AutomationDirect Productivity Suite project: Saginaw_ModbusRTU_v2 (software 3.11.0 (26))
author: charris
Rung notation: left to right = series (deeper-indented lines continue the line above), [a | b] = parallel branches, -- = plain wire, BOX.Pin = further input of the box above; 'quoted' = tag name, ? = field left empty; instruction and field names as stored in the project; options that are off are not listed.

HARDWARE
  Base 1 (5 slots)
    slot 0: P2-550

STRUCTURES
STRUCTURE read_Data
  net_Cool_SP : Int16, strLength=15
  net_HighTempAlmSP : Int16, strLength=15
  net_LowTempAlmSP : Int16, strLength=15
  net_Heat_SP : Int16, strLength=15
  net_Enable_Flags : Uint16, strLength=15
  Control_SP : Int16, strLength=15
  High_Temp_SP : Int16, strLength=15
  Low_Temp_SP : Int16, strLength=15
  Heater_SP : Int16, strLength=15
  Temp_POT : Int16, strLength=15
  Alarm_POT : Int16, strLength=15
  Heater_POT : Int16, strLength=15
  Control_Sensor : Int16, strLength=15
  State : Uint16, strLength=15
  Alarm_Stat : Uint16, strLength=15
  Output_Stat : Uint16, strLength=15
  Contact_Stat : Uint16, strLength=15
  IntAir_Outlet_Temp : Int16, strLength=15
  Ambient_Temp : Int16, strLength=15
  Act_Spd_int_Blow : Uint16, strLength=15
  Act_Spd_Amb_Blow : Uint16, strLength=15
  Act_Spd_Compress : Uint16, strLength=15
  Set_Spd_int_Blow : Uint16, strLength=15
  Set_Spd_Amb_Blow : Uint16, strLength=15
  Set_Spd_Compress : Uint16, strLength=15
  Alm_int_Blow : Uint16, strLength=15
  Alm_Amb_Blow : Uint16, strLength=15
  Alm_Compress : Uint16, strLength=15
STRUCTURE write_Data
  net_Cool_SP : Int16, strLength=15
  net_HighTempAlmSP : Int16, strLength=15
  net_LowTempAlmSP : Int16, strLength=15
  net_Heat_SP : Int16, strLength=15
  net_Enable_Flags : Uint16, strLength=15

TAGS  (name : type @system ID = initial value)
  readBuff1 : Array[50] of Uint16 @AR1US16-000001
  readBuff2 : Array[50] of Uint16 @AR1US16-000002
  readUnit1 : read_Data @USTRUC-000001
  readUnit2 : read_Data @USTRUC-000002
  writeUnit1 : write_Data @USTRUC-000003
  writeUnit2 : write_Data @USTRUC-000004
  writeBuff1 : Array[10] of Uint16 @AR1US16-000003
  writeBuff2 : Array[10] of Uint16 @AR1US16-000004
  Synch_Unit1_SP_Data : Boolean @C-000017
  Update_Unit1_SP : Boolean @C-000018
  Unit1_New_CoolSP : Int16 @S16-000037
  Update_Unit1_Flags : Boolean @C-000024
  Synch_Unit2_SP_Data : Boolean @C-000030
  Update_Unit2_SP : Boolean @C-000031
  Unit2_New_CoolSP : Int16 @S16-000038
  Update_Unit2_Flags : Boolean @C-000037
  Change_Node_Address : Boolean @C-000043
  Node_Number : Uint16 @US16-000031
  Write_Node_Number : Boolean @C-000044
  NodeNum_PrepWrite_Succ : Boolean @C-000050
  Disable_Reads : Boolean @C-000051
  Unit1_OutStat_AmbBlower : Boolean @C-000052
  Unit1_OutStat_Compressor : Boolean @C-000053
  Unit1_OutStat_Heater : Boolean @C-000054
  Unit1_OutStat_IntBlower : Boolean @C-000055
  EnableFlags : Int16 @S16-000039

SYSTEM TAGS USED OR MAPPED TO MODBUS
  'First Scan Bit' : Boolean @SBR-001003  // On during first scan in Run or Debug mode
  rComSuccessCNT : SCNT @SSTRUC-000001  // System Structure for Simple Counter
  rComErrorCNT : SCNT @SSTRUC-000002  // System Structure for Simple Counter
  ComSequenceTMR : STMR @SSTRUC-000003  // System Structure for Simple Timer
  ComSequenceCNT : SCNT @SSTRUC-000004  // System Structure for Simple Counter
  MRXUnit1 : MRX @SSTRUC-000005  // System Structure for Modbus Read
  MRXUnit2 : MRX @SSTRUC-000006  // System Structure for Modbus Read
  MWX_Chg_Node : MWX @SSTRUC-000013  // System Structure for Modbus Write
  MWXUnit1 : MWX @SSTRUC-000014  // System Structure for Modbus Write
  MWXUnit1b : MWX @SSTRUC-000015  // System Structure for Modbus Write
  MWXUnit2 : MWX @SSTRUC-000016  // System Structure for Modbus Write
  MWXUnit2b : MWX @SSTRUC-000017  // System Structure for Modbus Write

TASK 'Read/Write Data'  (Run Every Scan)
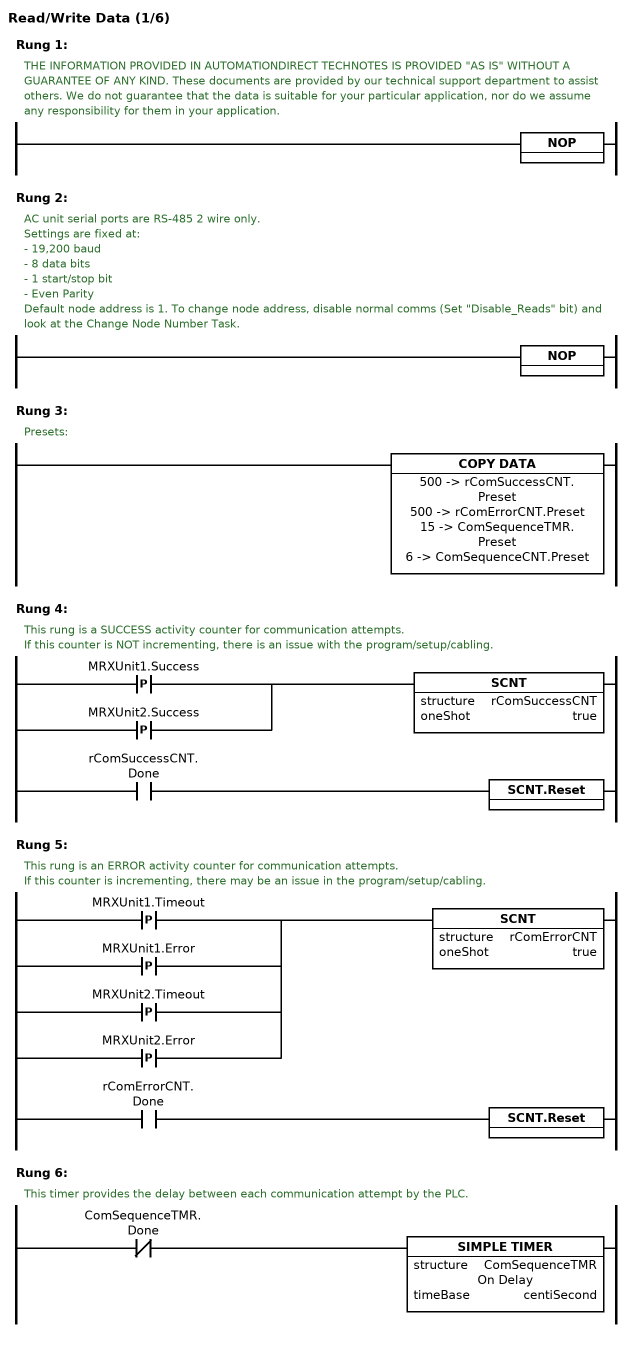
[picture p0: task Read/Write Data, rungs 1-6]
Rung 1:
  // THE INFORMATION PROVIDED IN AUTOMATIONDIRECT TECHNOTES IS PROVIDED "AS IS" WITHOUT A GUARANTEE OF ANY KIND. These documents are provided by our technical support department to assist others. We do not guarantee that the data is suitable for your particular application, nor do we assume any responsibility for them in your application.
  NOP()
Rung 2:
  // AC unit serial ports are RS-485 2 wire only.
  // Settings are fixed at:
  // - 19,200 baud
  // - 8 data bits
  // - 1 start/stop bit
  // - Even Parity
  // Default node address is 1. To change node address, disable normal comms (Set "Disable_Reads" bit) and look at the Change Node Number Task.
  NOP()
Rung 3:
  // Presets:
  CPY(500 -> rComSuccessCNT.Preset, 500 -> rComErrorCNT.Preset, 15 -> ComSequenceTMR.Preset, 6 -> ComSequenceCNT.Preset)
Rung 4:
  // This rung is a SUCCESS activity counter for communication attempts.
  // If this counter is NOT incrementing, there is an issue with the program/setup/cabling.
  [NOE(MRXUnit1.Success, rising) | NOE(MRXUnit2.Success, rising)] SCNT(structure=rComSuccessCNT, oneShot)
  NO(rComSuccessCNT.Done) SCNT.Reset
Rung 5:
  // This rung is an ERROR activity counter for communication attempts.
  // If this counter is incrementing, there may be an issue in the program/setup/cabling.
  [ NOE(MRXUnit1.Timeout, rising)
    | NOE(MRXUnit1.Error, rising)
    | NOE(MRXUnit2.Timeout, rising)
    | NOE(MRXUnit2.Error, rising) ]
    SCNT(structure=rComErrorCNT, oneShot)
  NO(rComErrorCNT.Done) SCNT.Reset
Rung 6:
  // This timer provides the delay between each communication attempt by the PLC.
  NC(ComSequenceTMR.Done) STMR(structure=ComSequenceTMR, on-delay, timeBase=centiSecond)
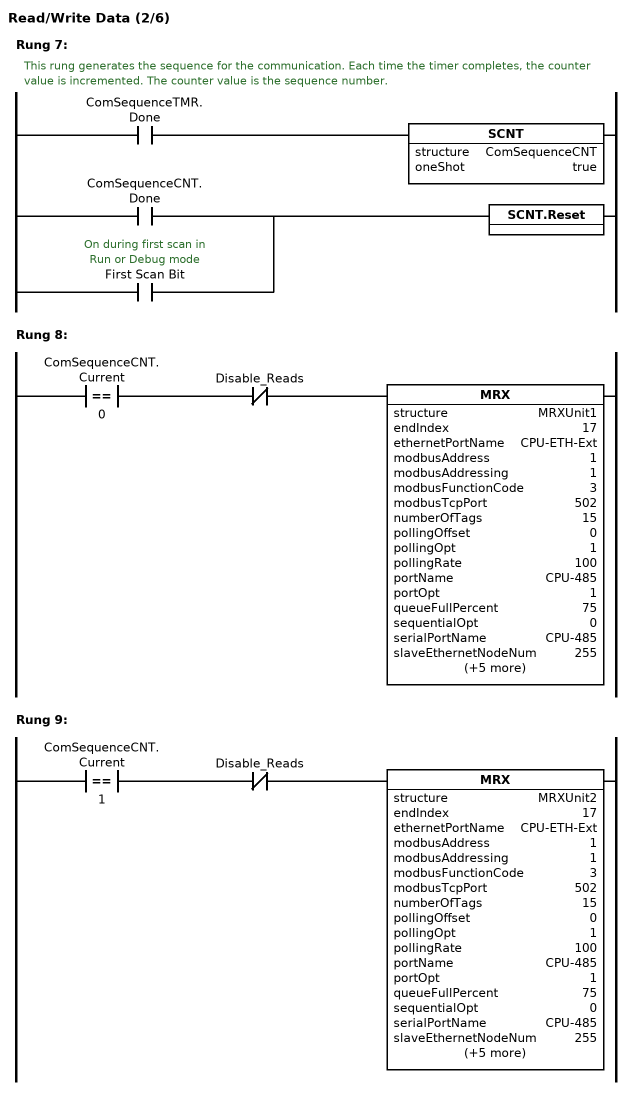
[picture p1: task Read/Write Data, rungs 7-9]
Rung 7:
  // This rung generates the sequence for the communication. Each time the timer completes, the counter value is incremented. The counter value is the sequence number.
  NO(ComSequenceTMR.Done) SCNT(structure=ComSequenceCNT, oneShot)
  [NO(ComSequenceCNT.Done) | NO('First Scan Bit')] SCNT.Reset
Rung 8:
  COMP(ComSequenceCNT.Current = 0) NC(Disable_Reads)
    MRX(structure=MRXUnit1, endIndex=17, ethernetPortName=CPU-ETH-Ext, modbusAddress=1, modbusAddressing=1, modbusFunctionCode=3, modbusTcpPort=502, numberOfTags=15, pollingOffset=0, pollingOpt=1, pollingRate=100, portName=CPU-485, portOpt=1, queueFullPercent=75, sequentialOpt=0, serialPortName=CPU-485, slaveEthernetNodeNum=255, slaveSerialNodeNum=1, startTag=readBuff1, startingIndex=1, stringLength=2, wordSwap)
Rung 9:
  COMP(ComSequenceCNT.Current = 1) NC(Disable_Reads)
    MRX(structure=MRXUnit2, endIndex=17, ethernetPortName=CPU-ETH-Ext, modbusAddress=1, modbusAddressing=1, modbusFunctionCode=3, modbusTcpPort=502, numberOfTags=15, pollingOffset=0, pollingOpt=1, pollingRate=100, portName=CPU-485, portOpt=1, queueFullPercent=75, sequentialOpt=0, serialPortName=CPU-485, slaveEthernetNodeNum=255, slaveSerialNodeNum=2, startTag=readBuff2, startingIndex=1, stringLength=2, wordSwap)
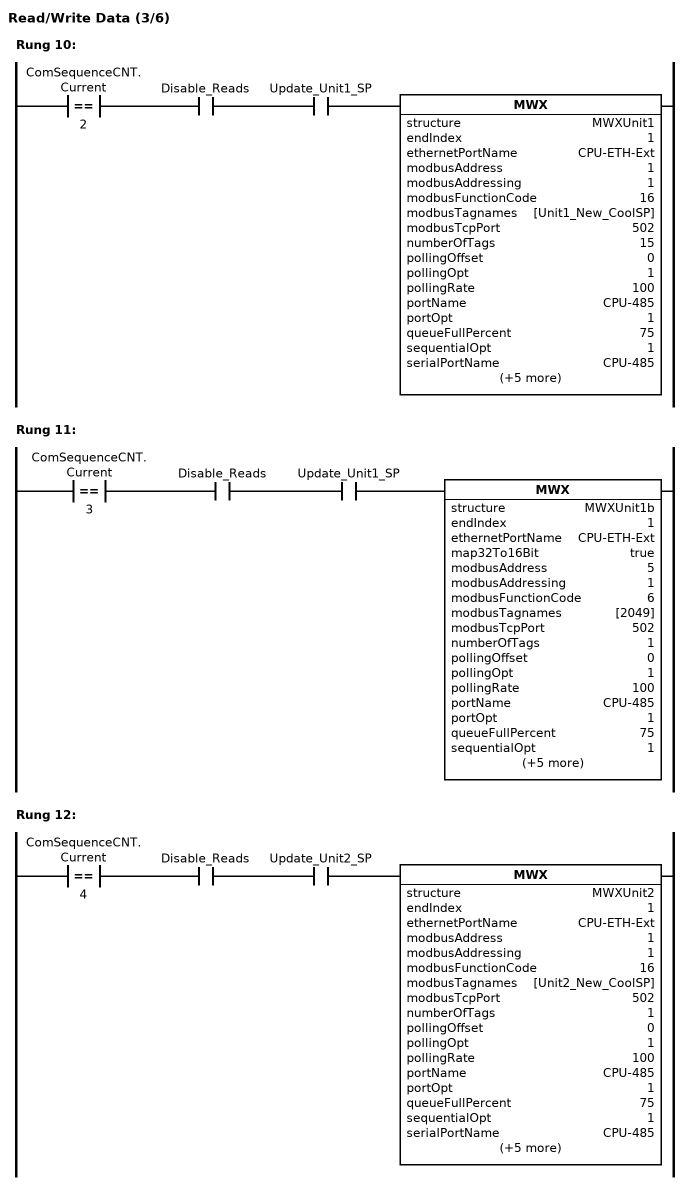
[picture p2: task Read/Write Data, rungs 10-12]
Rung 10:
  COMP(ComSequenceCNT.Current = 2) NO(Disable_Reads) NO(Update_Unit1_SP)
    MWX(structure=MWXUnit1, endIndex=1, ethernetPortName=CPU-ETH-Ext, modbusAddress=1, modbusAddressing=1, modbusFunctionCode=16, modbusTagnames=[Unit1_New_CoolSP], modbusTcpPort=502, numberOfTags=15, pollingOffset=0, pollingOpt=1, pollingRate=100, portName=CPU-485, portOpt=1, queueFullPercent=75, sequentialOpt=1, serialPortName=CPU-485, slaveEthernetNodeNum=255, slaveSerialNodeNum=1, startingIndex=1, stringLength=2, wordSwap)
Rung 11:
  COMP(ComSequenceCNT.Current = 3) NO(Disable_Reads) NO(Update_Unit1_SP)
    MWX(structure=MWXUnit1b, endIndex=1, ethernetPortName=CPU-ETH-Ext, map32To16Bit, modbusAddress=5, modbusAddressing=1, modbusFunctionCode=6, modbusTagnames=[2049], modbusTcpPort=502, numberOfTags=1, pollingOffset=0, pollingOpt=1, pollingRate=100, portName=CPU-485, portOpt=1, queueFullPercent=75, sequentialOpt=1, serialPortName=CPU-485, slaveEthernetNodeNum=255, slaveSerialNodeNum=1, startingIndex=1, stringLength=2)
Rung 12:
  COMP(ComSequenceCNT.Current = 4) NO(Disable_Reads) NO(Update_Unit2_SP)
    MWX(structure=MWXUnit2, endIndex=1, ethernetPortName=CPU-ETH-Ext, modbusAddress=1, modbusAddressing=1, modbusFunctionCode=16, modbusTagnames=[Unit2_New_CoolSP], modbusTcpPort=502, numberOfTags=1, pollingOffset=0, pollingOpt=1, pollingRate=100, portName=CPU-485, portOpt=1, queueFullPercent=75, sequentialOpt=1, serialPortName=CPU-485, slaveEthernetNodeNum=255, slaveSerialNodeNum=2, startingIndex=1, stringLength=2, wordSwap)
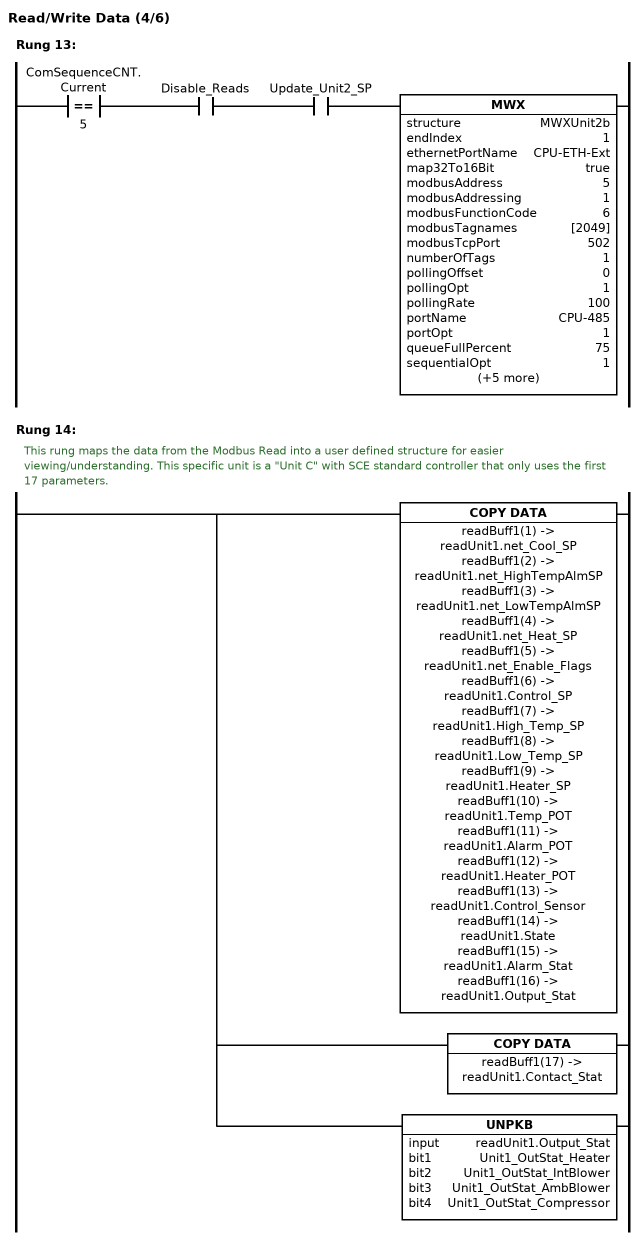
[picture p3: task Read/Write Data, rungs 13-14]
Rung 13:
  COMP(ComSequenceCNT.Current = 5) NO(Disable_Reads) NO(Update_Unit2_SP)
    MWX(structure=MWXUnit2b, endIndex=1, ethernetPortName=CPU-ETH-Ext, map32To16Bit, modbusAddress=5, modbusAddressing=1, modbusFunctionCode=6, modbusTagnames=[2049], modbusTcpPort=502, numberOfTags=1, pollingOffset=0, pollingOpt=1, pollingRate=100, portName=CPU-485, portOpt=1, queueFullPercent=75, sequentialOpt=1, serialPortName=CPU-485, slaveEthernetNodeNum=255, slaveSerialNodeNum=2, startingIndex=1, stringLength=2)
Rung 14:
  // This rung maps the data from the Modbus Read into a user defined structure for easier viewing/understanding. This specific unit is a "Unit C" with SCE standard controller that only uses the first 17 parameters.
  CPY(readBuff1(1) -> readUnit1.net_Cool_SP, readBuff1(2) -> readUnit1.net_HighTempAlmSP, readBuff1(3) -> readUnit1.net_LowTempAlmSP, readBuff1(4) -> readUnit1.net_Heat_SP, readBuff1(5) -> readUnit1.net_Enable_Flags, readBuff1(6) -> readUnit1.Control_SP, readBuff1(7) -> readUnit1.High_Temp_SP, readBuff1(8) -> readUnit1.Low_Temp_SP, readBuff1(9) -> readUnit1.Heater_SP, readBuff1(10) -> readUnit1.Temp_POT, readBuff1(11) -> readUnit1.Alarm_POT, readBuff1(12) -> readUnit1.Heater_POT, readBuff1(13) -> readUnit1.Control_Sensor, readBuff1(14) -> readUnit1.State, readBuff1(15) -> readUnit1.Alarm_Stat, readBuff1(16) -> readUnit1.Output_Stat)
  CPY(readBuff1(17) -> readUnit1.Contact_Stat)
  UNPKB(input=readUnit1.Output_Stat, bit1=Unit1_OutStat_Heater, bit2=Unit1_OutStat_IntBlower, bit3=Unit1_OutStat_AmbBlower, bit4=Unit1_OutStat_Compressor)
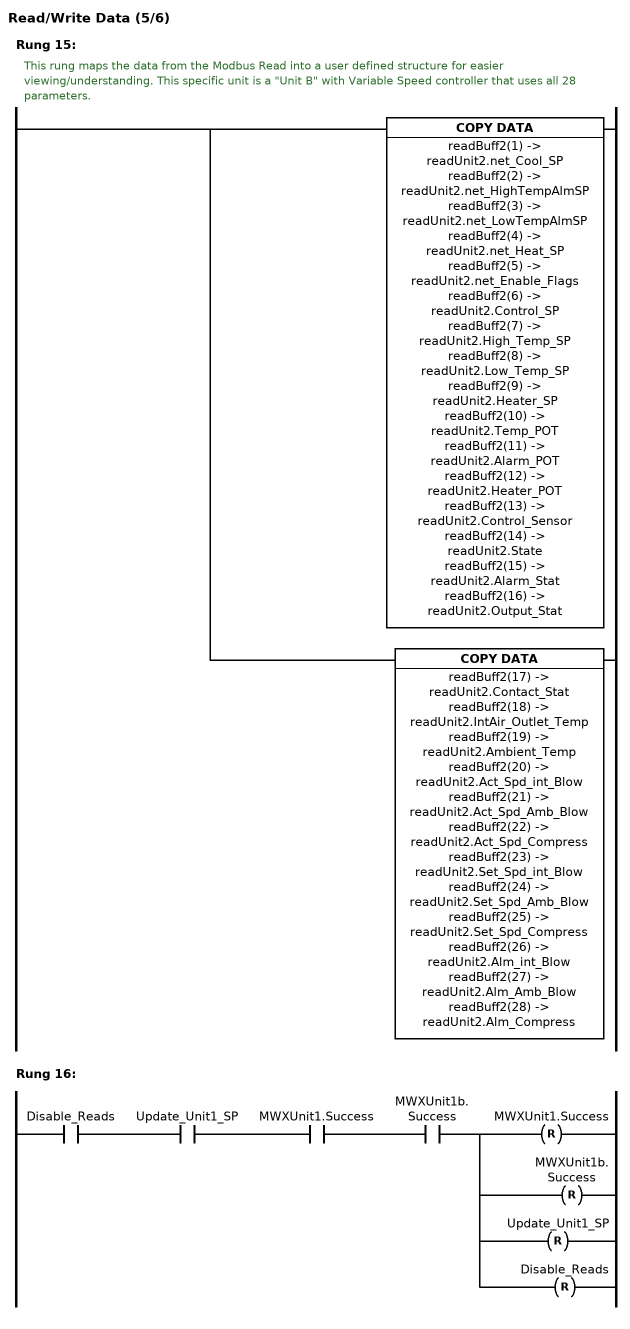
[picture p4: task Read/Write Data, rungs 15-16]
Rung 15:
  // This rung maps the data from the Modbus Read into a user defined structure for easier viewing/understanding. This specific unit is a "Unit B" with Variable Speed controller that uses all 28 parameters.
  CPY(readBuff2(1) -> readUnit2.net_Cool_SP, readBuff2(2) -> readUnit2.net_HighTempAlmSP, readBuff2(3) -> readUnit2.net_LowTempAlmSP, readBuff2(4) -> readUnit2.net_Heat_SP, readBuff2(5) -> readUnit2.net_Enable_Flags, readBuff2(6) -> readUnit2.Control_SP, readBuff2(7) -> readUnit2.High_Temp_SP, readBuff2(8) -> readUnit2.Low_Temp_SP, readBuff2(9) -> readUnit2.Heater_SP, readBuff2(10) -> readUnit2.Temp_POT, readBuff2(11) -> readUnit2.Alarm_POT, readBuff2(12) -> readUnit2.Heater_POT, readBuff2(13) -> readUnit2.Control_Sensor, readBuff2(14) -> readUnit2.State, readBuff2(15) -> readUnit2.Alarm_Stat, readBuff2(16) -> readUnit2.Output_Stat)
  CPY(readBuff2(17) -> readUnit2.Contact_Stat, readBuff2(18) -> readUnit2.IntAir_Outlet_Temp, readBuff2(19) -> readUnit2.Ambient_Temp, readBuff2(20) -> readUnit2.Act_Spd_int_Blow, readBuff2(21) -> readUnit2.Act_Spd_Amb_Blow, readBuff2(22) -> readUnit2.Act_Spd_Compress, readBuff2(23) -> readUnit2.Set_Spd_int_Blow, readBuff2(24) -> readUnit2.Set_Spd_Amb_Blow, readBuff2(25) -> readUnit2.Set_Spd_Compress, readBuff2(26) -> readUnit2.Alm_int_Blow, readBuff2(27) -> readUnit2.Alm_Amb_Blow, readBuff2(28) -> readUnit2.Alm_Compress)
Rung 16:
  NO(Disable_Reads) NO(Update_Unit1_SP) NO(MWXUnit1.Success) NO(MWXUnit1b.Success)
    [RST(MWXUnit1.Success) | RST(MWXUnit1b.Success) | RST(Update_Unit1_SP) | RST(Disable_Reads)]
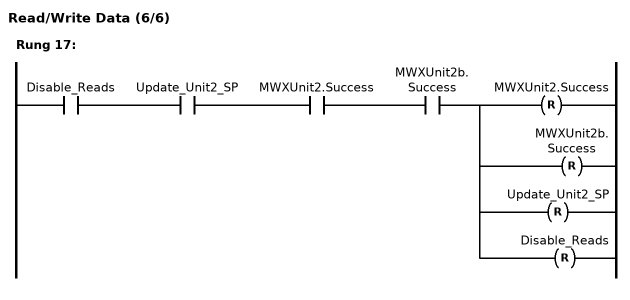
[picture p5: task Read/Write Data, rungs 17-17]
Rung 17:
  NO(Disable_Reads) NO(Update_Unit2_SP) NO(MWXUnit2.Success) NO(MWXUnit2b.Success)
    [RST(MWXUnit2.Success) | RST(MWXUnit2b.Success) | RST(Update_Unit2_SP) | RST(Disable_Reads)]

TASK 'Change Node Number'  (Run Every Scan)
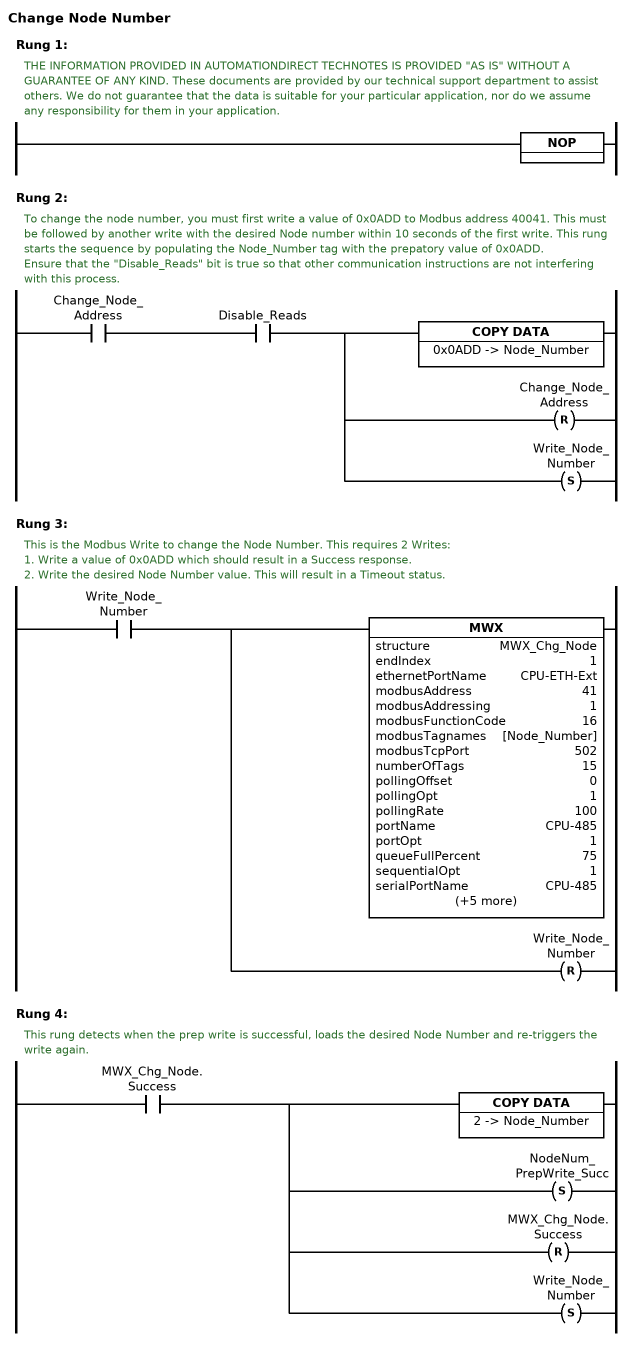
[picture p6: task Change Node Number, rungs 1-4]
Rung 1:
  // THE INFORMATION PROVIDED IN AUTOMATIONDIRECT TECHNOTES IS PROVIDED "AS IS" WITHOUT A GUARANTEE OF ANY KIND. These documents are provided by our technical support department to assist others. We do not guarantee that the data is suitable for your particular application, nor do we assume any responsibility for them in your application.
  NOP()
Rung 2:
  // To change the node number, you must first write a value of 0x0ADD to Modbus address 40041. This must be followed by another write with the desired Node number within 10 seconds of the first write. This rung starts the sequence by populating the Node_Number tag with the prepatory value of 0x0ADD.
  // Ensure that the "Disable_Reads" bit is true so that other communication instructions are not interfering with this process.
  NO(Change_Node_Address) NO(Disable_Reads)
    [CPY(0x0ADD -> Node_Number) | RST(Change_Node_Address) | SET(Write_Node_Number)]
Rung 3:
  // This is the Modbus Write to change the Node Number. This requires 2 Writes:
  // 1. Write a value of 0x0ADD which should result in a Success response.
  // 2. Write the desired Node Number value. This will result in a Timeout status.
  NO(Write_Node_Number)
    [ MWX(structure=MWX_Chg_Node, endIndex=1, ethernetPortName=CPU-ETH-Ext, modbusAddress=41, modbusAddressing=1, modbusFunctionCode=16, modbusTagnames=[Node_Number], modbusTcpPort=502, numberOfTags=15, pollingOffset=0, pollingOpt=1, pollingRate=100, portName=CPU-485, portOpt=1, queueFullPercent=75, sequentialOpt=1, serialPortName=CPU-485, slaveEthernetNodeNum=255, slaveSerialNodeNum=1, startingIndex=1, stringLength=2, wordSwap)
    | RST(Write_Node_Number) ]
Rung 4:
  // This rung detects when the prep write is successful, loads the desired Node Number and re-triggers the write again.
  NO(MWX_Chg_Node.Success)
    [CPY(2 -> Node_Number) | SET(NodeNum_PrepWrite_Succ) | RST(MWX_Chg_Node.Success) | SET(Write_Node_Number)]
